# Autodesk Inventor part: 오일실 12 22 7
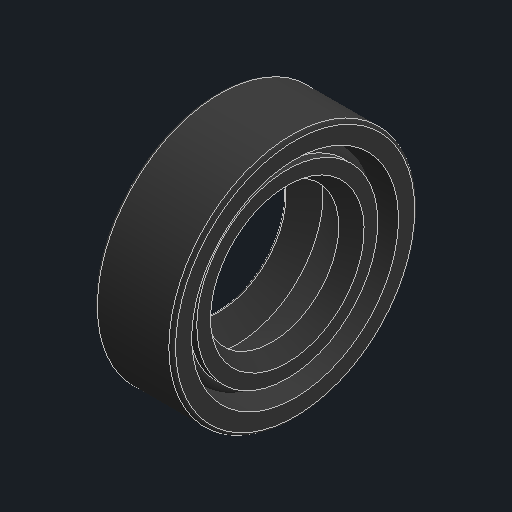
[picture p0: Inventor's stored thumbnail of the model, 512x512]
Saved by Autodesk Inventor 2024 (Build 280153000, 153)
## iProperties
Created: 2024-05
Part Number: 오일실 12 22 7
Material: 고무
Description: 오일-실
Document SubType Name: Modeling
Designer: kh_501
Density: 0.93 g/cm^3
Appearance: 기본값
Author: jhkim
Sending System: Autodesk Inventor 2025
Preprocessor: ST-DEVELOPER v20
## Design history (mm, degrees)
node "오일실 12 22 71"
node "솔리드1"
body "Solid1"
